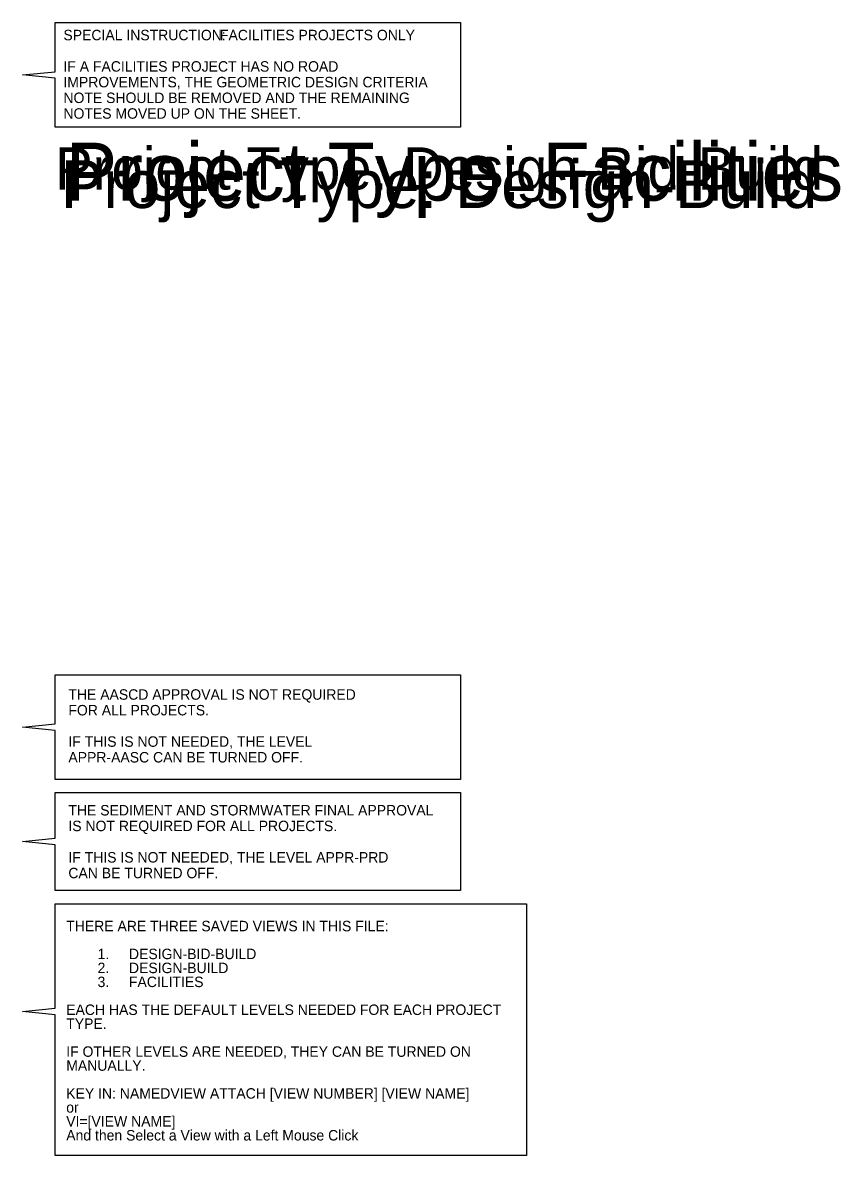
# Model space of a CAD drawing. Extents: x -8.7 to 49.9, y 0 to 23.8.
# Drawn here: x 34.25 to 49.89, y 0.06 to 21.72 of the extents above; entities that cross this region are included whole.
import ezdxf

# ---------------------------------------------------------------- set-up
doc = ezdxf.new("R2010")
doc.units = 0
for name, color, linetype in [('G-ANNO-DENG', 7, 'Continuous'), ('G-PRTY-DBLD', 7, 'Continuous'), ('G-PRTY-FACL', 7, 'Continuous'), ('G-USER-LINE', 7, 'Continuous'), ('G-USER-TEXT', 7, 'Continuous')]:
    doc.layers.add(name, color=color, linetype=linetype)

msp = doc.modelspace()

# ---------------------------------------------------------------- linework, layer by layer
at = {"layer": 'G-USER-LINE'}
for points in [[(34.875, 20.657), (34.25, 20.72), (34.875, 20.782), (34.875, 21.72), (42.625, 21.72), (42.625, 19.72), (34.875, 19.72)], [(34.875, 8.188), (34.25, 8.25), (34.875, 8.312), (34.875, 9.25), (42.625, 9.25), (42.625, 7.25), (34.875, 7.25)], [(34.875, 6), (34.25, 6.062), (34.875, 6.125), (34.875, 7), (42.625, 7), (42.625, 5.125), (34.875, 5.125)], [(34.875, 2.75), (34.25, 2.812), (34.875, 2.875), (34.875, 4.875), (43.89, 4.875), (43.89, 0.064), (34.875, 0.064)]]:
    msp.add_lwpolyline(points, close=True, dxfattribs=at)

# ---------------------------------------------------------------- texts
at = {"layer": 'G-ANNO-DENG'}
msp.add_text('Project Type: Design-Bid-Build', height=0.80703, dxfattribs=at).set_placement((34.87, 18.528))
at = {"layer": 'G-PRTY-DBLD'}
msp.add_text('Project Type: Design-Build', height=0.91412, dxfattribs=at).set_placement((34.98, 18.176))
at = {"layer": 'G-PRTY-FACL'}
msp.add_text('Project Type: Facilities', height=1.10588, dxfattribs=at).set_placement((35.072, 18.318))
at = {"layer": 'G-USER-TEXT'}
for s, p in [('SPECIAL INSTRUCTION:', (35.03, 21.383)), (' FACILITIES PROJECTS ONLY', (37.951, 21.383)), ('IF A FACILITIES PROJECT HAS NO ROAD ', (35.03, 20.783)), ('IMPROVEMENTS, THE GEOMETRIC DESIGN CRITERIA ', (35.03, 20.483)), ('NOTE SHOULD BE REMOVED AND THE REMAINING ', (35.03, 20.183)), ('NOTES MOVED UP ON THE SHEET.', (35.03, 19.883)), ('THE AASCD APPROVAL IS NOT REQUIRED', (35.125, 8.775)), ('FOR ALL PROJECTS.', (35.125, 8.475)), ('IF THIS IS NOT NEEDED, THE LEVEL', (35.125, 7.875)), ('APPR-AASC CAN BE TURNED OFF.', (35.125, 7.575)), ('THE SEDIMENT AND STORMWATER FINAL APPROVAL ', (35.125, 6.562)), ('IS NOT REQUIRED FOR ALL PROJECTS.', (35.125, 6.262)), ('IF THIS IS NOT NEEDED, THE LEVEL APPR-PRD ', (35.125, 5.662)), ('CAN BE TURNED OFF.', (35.125, 5.362)), ('THERE ARE THREE SAVED VIEWS IN THIS FILE:', (35.084, 4.348)), ('1.', (35.684, 3.815)), ('DESIGN-BID-BUILD', (36.284, 3.815)), ('2.', (35.684, 3.548)), ('DESIGN-BUILD', (36.284, 3.548)), ('3.', (35.684, 3.281)), ('FACILITIES', (36.284, 3.281)), ('EACH HAS THE DEFAULT LEVELS NEEDED FOR EACH PROJECT ', (35.084, 2.748)), ('TYPE.', (35.084, 2.481)), ('IF OTHER LEVELS ARE NEEDED, THEY CAN BE TURNED ON ', (35.084, 1.948)), ('MANUALLY.', (35.084, 1.681)), ('KEY IN: NAMEDVIEW ATTACH [VIEW NUMBER] [VIEW NAME]', (35.084, 1.148)), ('or ', (35.084, 0.881)), ('VI=[VIEW NAME]', (35.084, 0.615)), ('And then Select a View with a Left Mouse Click', (35.084, 0.348))]:
    msp.add_text(s, height=0.2, dxfattribs=at).set_placement(p)

doc.saveas('drawing.dxf')
